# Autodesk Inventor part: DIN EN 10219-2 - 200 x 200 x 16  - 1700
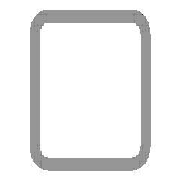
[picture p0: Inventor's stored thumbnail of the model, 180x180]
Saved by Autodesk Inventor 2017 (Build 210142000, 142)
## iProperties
Created: 2017-11
Part Number: DIN EN 10219-2 - 200 x 200 x 16  - 1700
Material: Steel, Mild
Description: Cold formed welded structural hollow sections of non-alloy and fine grain structural steel
Document SubType Name: Modeling
Standard: DIN
Designer: iusti
Standard Revision: 2006-07
Standards Organization: DIN
Language: en-US
Size Designation: 200 x 200 x 16
Categories: <MemberInstance><Categories><Category DisplayName="Structural Shapes" InternalName="089c4875-fa83-4c05-b084-43b9cc11f5ed" Mnemonic="GRDR"><CategoryParameter Dis
Stock Number: 200 x 200 x 16
Density: 7.85 g/cm^3
Appearance: Semi-Polished
Mass: 125724 g
Surface Area: 20321.8 cm^2
Volume: 16015.9 cm^3
G_L: 1700.000 mm
G_W: 200.000 mm
G_H: 200.000 mm
+81F2769D-CBCB-4BAE-9991-99821565208A+CUTDETAIL1: Miter 45.00 deg
+00569EB8-A9A7-487F-AD20-8A8F135713C5+CUTDETAIL2: Miter 45.00 deg
_CCFamilyMember: 103
_CCFamilyDisplayName: DIN EN 10219-2 (Square Hollow Section - Cold Formed) - Cold formed welded structural hollow sections of non-alloy and fine grain structural steel
_FrameMemberDoc: Frame Member File
_Version: 15.0.0
_GetPNFromCC: 1
Author: iusti
IsCustomPart: 1
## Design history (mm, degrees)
node "Start plane"
node "End plane"
sketch "Sketch"
  geometry: L1 (-100, -52)-(-100, 52); L2 (-52, 100)-(52, 100); L3 (100, 52)-(100, -52); L4 (52, -100)-(-52, -100); L5 (-52, 84)-(52, 84); L6 (84, 52)-(84, -52); L7 (52, -84)-(-52, -84); L8 (-84, -52)-(-84, 52); L9 (0, 153.918)-(0, -153.918) reference; L10 (-153.918, 0)-(153.918, 0) reference; A1 r 48 centre (-52, -52) between (-100, -52) and (-52, -100); A2 r 48 centre (-52, 52) between (-52, 100) and (-100, 52); A3 r 48 centre (52, 52) between (100, 52) and (52, 100); A4 r 48 centre (52, -52) between (52, -100) and (100, -52); A5 r 32 centre (-52, 52) between (-52, 84) and (-84, 52); A6 r 32 centre (52, 52) between (84, 52) and (52, 84); A7 r 32 centre (52, -52) between (52, -84) and (84, -52); A8 r 32 centre (-52, -52) between (-84, -52) and (-52, -84)
  constraints: 16 end point, 16 point on circle, 8 centre point, 8 tangent, 4 parallel, 3 equal radius, 2 perpendicular, 7 other
  dimensions: "d7" = 48 radius of A1 (= G_IR); "d10" = 200 distance between parallel lines of L2 L4 (= G_H); "d11" = 200 distance between parallel lines of L1 L3 (= G_W); "d12" = 16 distance between parallel lines of L3 L6 (= G_T); "d15" = 100 distance between parallel lines of L2 L10 (= 0.5 x d10); "d16" = 100 distance between parallel lines of L9 L3 (= 0.5 x d11)
extrude "Body" new body sketch "Sketch" stored distance "d3" = 1700 (= G_L); taper "d4" = 0 deg
node "Driven Length"
  sketch "Sketch3"
    geometry: L1 (0, 0)-(10, 0) reference
    constraints: 2 end point, 1 horizontal
  workplane "Work Plane3"
  sketch "Sketch4"
    geometry: L1 (-2, -100)-(12, -100) reference; L2 (-2, 1600)-(12, 1600) reference
    dimensions: "d18" = 1700 distance between parallel lines of L1 L2 (derived)
workplane "Work Plane4"
split "Split1"
workplane "Work Plane5"
split "Split2"
body "Solid1"
other parameters: "G_W" = 200 [user parameter; used in 1 equation term], "G_H" = 200 [user parameter; used in 1 equation term], "G_T" = 16 [user parameter; used in 1 equation term], "G_IR" = 48 [user parameter; used in 1 equation term], "G_L" = 1700 (= d18) [user parameter; used in 1 equation term], "d17" = 90 deg
